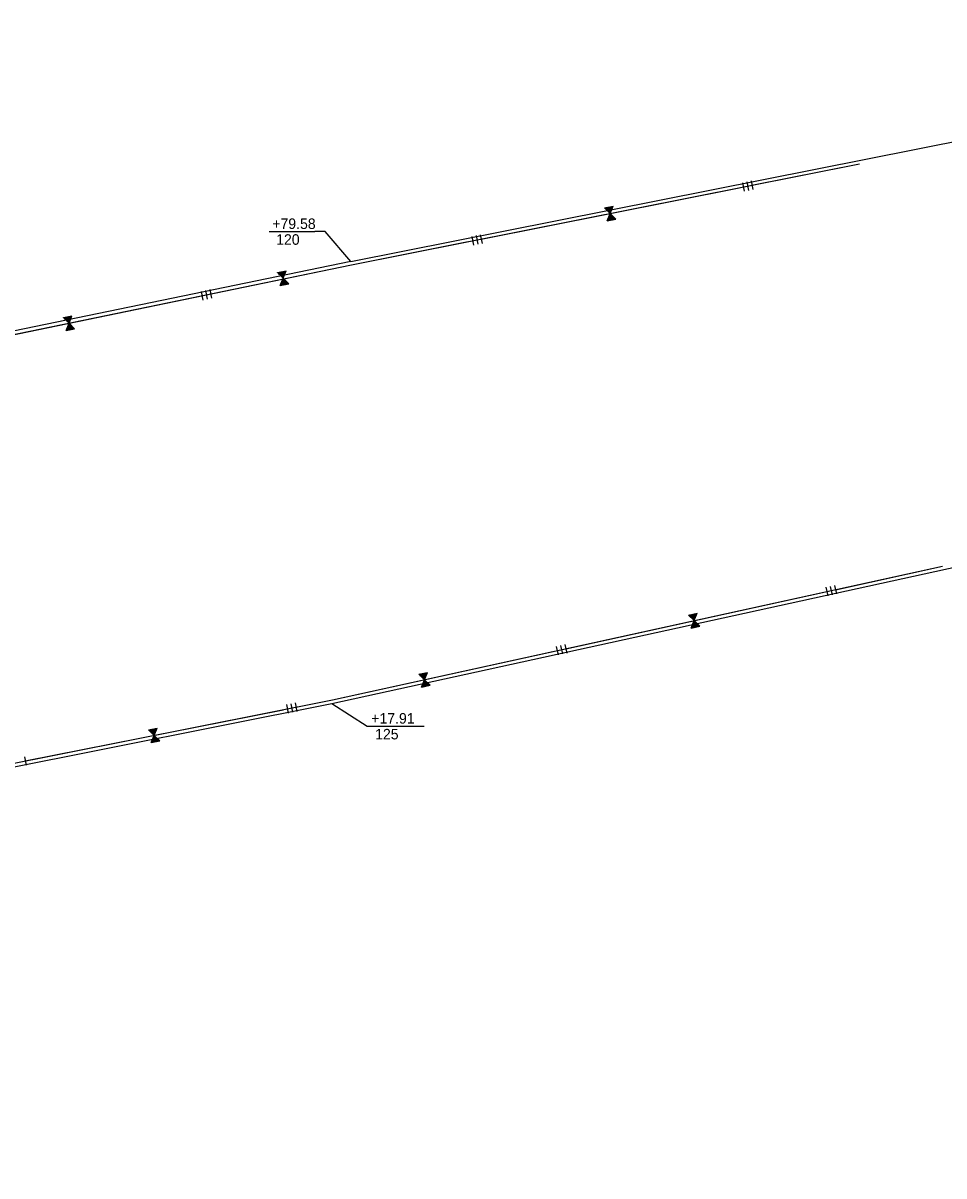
# Model space of a CAD drawing. Extents: x 979729 to 993523, y 1834148 to 1845433.
# Drawn here: x 986339 to 986865, y 1837768 to 1838426 of the extents above; entities that cross this region are included whole.
import ezdxf

# ---------------------------------------------------------------- set-up
doc = ezdxf.new("R2010")
doc.units = 0
for name, color, linetype in [('42', 7, 'Continuous'), ('51', 7, 'Continuous'), ('R_Draft', 7, 'Continuous')]:
    doc.layers.add(name, color=color, linetype=linetype)

msp = doc.modelspace()

# ---------------------------------------------------------------- linework, layer by layer
at = {"layer": '42'}
for p, q in [((986526.66, 1838287.95), (986816.42, 1838345.6)), ((986749.71, 1838334.87), (986750.68, 1838329.97)), ((986752.16, 1838335.36), (986753.13, 1838330.46)), ((986754.61, 1838335.85), (986755.59, 1838330.95)), ((986671, 1838320.49), (986674.18, 1838317.3)), ((986671.07, 1838320.45), (986671.09, 1838320.51)), ((986671.27, 1838320.27), (986671.39, 1838320.57)), ((986671.45, 1838320.06), (986671.68, 1838320.62)), ((986671.65, 1838319.89), (986671.98, 1838320.68)), ((986671.83, 1838319.68), (986672.27, 1838320.74)), ((986672.02, 1838319.47), (986672.57, 1838320.8)), ((986672.22, 1838319.3), (986672.86, 1838320.86)), ((986672.44, 1838319.18), (986673.09, 1838320.76)), ((986672.61, 1838318.94), (986673.45, 1838320.98)), ((986672.81, 1838318.77), (986673.74, 1838321.03)), ((986672.98, 1838318.53), (986674.04, 1838321.09)), ((986673.19, 1838318.38), (986674.33, 1838321.15)), ((986673.36, 1838318.15), (986674.63, 1838321.21)), ((986673.56, 1838317.98), (986674.92, 1838321.27)), ((986673.75, 1838317.76), (986675.22, 1838321.33)), ((986673.96, 1838317.62), (986675.51, 1838321.39)), ((986674.13, 1838317.38), (986675.81, 1838321.44)), ((986674.18, 1838317.3), (986675.9, 1838321.46)), ((986672.46, 1838313.13), (986674.18, 1838317.3)), ((986672.51, 1838313.2), (986672.56, 1838313.15)), ((986672.63, 1838313.43), (986672.85, 1838313.21)), ((986672.72, 1838313.7), (986673.14, 1838313.27)), ((986672.83, 1838313.93), (986673.44, 1838313.33)), ((986672.92, 1838314.2), (986673.73, 1838313.39)), ((986673.01, 1838314.46), (986674.03, 1838313.44)), ((986673.13, 1838314.7), (986674.32, 1838313.5)), ((986673.29, 1838314.89), (986674.5, 1838313.68)), ((986673.36, 1838315.18), (986674.91, 1838313.62)), ((986673.48, 1838315.41), (986675.21, 1838313.68)), ((986673.54, 1838315.7), (986675.5, 1838313.74)), ((986673.68, 1838315.92), (986675.8, 1838313.8)), ((986673.75, 1838316.2), (986676.09, 1838313.85)), ((986673.87, 1838316.44), (986676.39, 1838313.91)), ((986673.96, 1838316.7), (986676.68, 1838313.97)), ((986674.1, 1838316.92), (986676.98, 1838314.03)), ((986674.16, 1838317.2), (986677.27, 1838314.09)), ((986674.18, 1838317.3), (986677.37, 1838314.11)), ((986597.69, 1838304.63), (986598.66, 1838299.72)), ((986600.14, 1838305.11), (986601.11, 1838300.21)), ((986595.23, 1838304.14), (986596.21, 1838299.23)), ((985983.54, 1838175.82), (986526.67, 1838287.95)), ((986487.41, 1838280.68), (986488.94, 1838284.45)), ((986487.58, 1838280.44), (986489.23, 1838284.52)), ((986487.64, 1838280.36), (986489.33, 1838284.54)), ((986484.43, 1838283.52), (986487.64, 1838280.36)), ((986484.5, 1838283.48), (986484.52, 1838283.54)), ((986484.7, 1838283.31), (986484.82, 1838283.6)), ((986484.88, 1838283.1), (986485.11, 1838283.66)), ((986485.09, 1838282.93), (986485.41, 1838283.73)), ((986485.27, 1838282.72), (986485.7, 1838283.79)), ((986485.46, 1838282.51), (986486, 1838283.85)), ((986485.66, 1838282.34), (986486.29, 1838283.91)), ((986485.88, 1838282.23), (986486.52, 1838283.81)), ((986485.95, 1838276.18), (986487.64, 1838280.36)), ((986486.05, 1838281.99), (986486.88, 1838284.03)), ((986486.25, 1838281.82), (986487.17, 1838284.09)), ((986486.43, 1838281.58), (986487.47, 1838284.15)), ((986486.64, 1838281.44), (986487.76, 1838284.21)), ((986486.77, 1838277.94), (986487.98, 1838276.74)), ((986486.81, 1838281.2), (986488.06, 1838284.27)), ((986486.83, 1838278.23), (986488.39, 1838276.68)), ((986486.94, 1838278.47), (986488.69, 1838276.75)), ((986487.01, 1838281.03), (986488.35, 1838284.33)), ((986487.01, 1838278.75), (986488.98, 1838276.81)), ((986487.15, 1838278.97), (986489.28, 1838276.87)), ((986487.2, 1838280.82), (986488.64, 1838284.39)), ((986487.21, 1838279.26), (986489.57, 1838276.93)), ((986487.33, 1838279.49), (986489.87, 1838276.99)), ((986487.42, 1838279.76), (986490.16, 1838277.05)), ((986487.55, 1838279.97), (986490.45, 1838277.11)), ((986487.62, 1838280.26), (986490.75, 1838277.17)), ((986487.64, 1838280.36), (986490.85, 1838277.19)), ((986440.88, 1838272.79), (986441.89, 1838267.89)), ((986443.33, 1838273.29), (986444.34, 1838268.4)), ((986445.78, 1838273.8), (986446.79, 1838268.9)), ((986485.99, 1838276.24), (986486.04, 1838276.2)), ((986486.11, 1838276.48), (986486.34, 1838276.26)), ((986486.2, 1838276.75), (986486.63, 1838276.32)), ((986486.31, 1838276.98), (986486.92, 1838276.38)), ((986486.4, 1838277.25), (986487.22, 1838276.44)), ((986486.49, 1838277.51), (986487.51, 1838276.5)), ((986486.6, 1838277.75), (986487.81, 1838276.56)), ((986363.31, 1838256.83), (986363.85, 1838258.16)), ((986363.51, 1838256.66), (986364.14, 1838258.22)), ((986363.73, 1838256.55), (986364.37, 1838258.13)), ((986363.9, 1838256.3), (986364.73, 1838258.34)), ((986364.1, 1838256.13), (986365.02, 1838258.4)), ((986364.28, 1838255.9), (986365.32, 1838258.47)), ((986364.49, 1838255.75), (986365.61, 1838258.53)), ((986364.66, 1838255.52), (986365.91, 1838258.59)), ((986364.86, 1838255.35), (986366.2, 1838258.65)), ((986365.05, 1838255.14), (986366.49, 1838258.71)), ((986365.26, 1838254.99), (986366.79, 1838258.77)), ((986365.43, 1838254.76), (986367.08, 1838258.83)), ((986365.49, 1838254.67), (986367.18, 1838258.85)), ((986362.28, 1838257.84), (986365.49, 1838254.67)), ((986362.35, 1838257.8), (986362.37, 1838257.86)), ((986362.55, 1838257.63), (986362.67, 1838257.92)), ((986362.73, 1838257.42), (986362.96, 1838257.98)), ((986362.94, 1838257.25), (986363.26, 1838258.04)), ((986363.12, 1838257.04), (986363.55, 1838258.1)), ((986363.8, 1838250.49), (986365.49, 1838254.67)), ((986364.25, 1838251.56), (986365.07, 1838250.76)), ((986364.34, 1838251.83), (986365.36, 1838250.82)), ((986364.45, 1838252.07), (986365.66, 1838250.88)), ((986364.62, 1838252.26), (986365.83, 1838251.06)), ((986364.68, 1838252.55), (986366.24, 1838251)), ((986364.79, 1838252.78), (986366.54, 1838251.06)), ((986364.86, 1838253.07), (986366.83, 1838251.12)), ((986365, 1838253.29), (986367.13, 1838251.18)), ((986365.06, 1838253.57), (986367.42, 1838251.24)), ((986365.18, 1838253.81), (986367.72, 1838251.3)), ((986365.27, 1838254.07), (986368.01, 1838251.36)), ((986365.4, 1838254.29), (986368.3, 1838251.42)), ((986365.47, 1838254.57), (986368.6, 1838251.48)), ((986365.49, 1838254.67), (986368.7, 1838251.51)), ((986363.84, 1838250.56), (986363.89, 1838250.51)), ((986363.96, 1838250.8), (986364.18, 1838250.57)), ((986364.05, 1838251.06), (986364.48, 1838250.63)), ((986364.16, 1838251.3), (986364.77, 1838250.7)), ((986515.73, 1838039.61), (986863.84, 1838115.91)), ((986797.33, 1838103.89), (986798.4, 1838099)), ((986799.77, 1838104.42), (986800.84, 1838099.54)), ((986802.21, 1838104.96), (986803.28, 1838100.07)), ((986718.92, 1838087.98), (986722.16, 1838084.85)), ((986718.98, 1838087.94), (986719.01, 1838088)), ((986719.19, 1838087.77), (986719.3, 1838088.06)), ((986719.37, 1838087.56), (986719.59, 1838088.13)), ((986719.58, 1838087.4), (986719.89, 1838088.19)), ((986719.76, 1838087.19), (986720.18, 1838088.26)), ((986719.95, 1838086.98), (986720.47, 1838088.32)), ((986720.15, 1838086.81), (986720.77, 1838088.39)), ((986720.38, 1838086.7), (986721, 1838088.3)), ((986720.55, 1838086.46), (986721.35, 1838088.52)), ((986720.76, 1838086.29), (986721.65, 1838088.58)), ((986720.93, 1838086.06), (986721.94, 1838088.64)), ((986721.15, 1838085.92), (986722.24, 1838088.71)), ((986721.32, 1838085.69), (986722.53, 1838088.77)), ((986721.52, 1838085.52), (986722.82, 1838088.84)), ((986721.71, 1838085.31), (986723.11, 1838088.9)), ((986721.93, 1838085.17), (986723.41, 1838088.97)), ((986722.1, 1838084.94), (986723.7, 1838089.03)), ((986722.16, 1838084.85), (986723.8, 1838089.05)), ((986720.52, 1838080.65), (986722.16, 1838084.85)), ((986720.56, 1838080.72), (986720.61, 1838080.67)), ((986720.68, 1838080.96), (986720.91, 1838080.74)), ((986720.76, 1838081.22), (986721.2, 1838080.8)), ((986720.88, 1838081.46), (986721.49, 1838080.87)), ((986720.96, 1838081.73), (986721.79, 1838080.93)), ((986721.04, 1838081.99), (986722.08, 1838081)), ((986721.16, 1838082.23), (986722.37, 1838081.06)), ((986721.32, 1838082.43), (986722.55, 1838081.24)), ((986721.37, 1838082.72), (986722.96, 1838081.19)), ((986721.49, 1838082.96), (986723.25, 1838081.25)), ((986721.55, 1838083.24), (986723.55, 1838081.32)), ((986721.68, 1838083.46), (986723.84, 1838081.38)), ((986721.75, 1838083.75), (986724.13, 1838081.45)), ((986721.86, 1838083.98), (986724.43, 1838081.51)), ((986721.95, 1838084.25), (986724.72, 1838081.57)), ((986722.08, 1838084.47), (986725.01, 1838081.64)), ((986722.14, 1838084.75), (986725.31, 1838081.7)), ((986722.16, 1838084.85), (986725.4, 1838081.73)), ((986643.48, 1838070.17), (986644.55, 1838065.28)), ((986645.92, 1838070.7), (986646.99, 1838065.82)), ((986648.36, 1838071.24), (986649.43, 1838066.35)), ((986565.07, 1838054.26), (986568.31, 1838051.13)), ((986565.13, 1838054.22), (986565.16, 1838054.28)), ((986565.34, 1838054.05), (986565.45, 1838054.34)), ((986565.52, 1838053.84), (986565.75, 1838054.41)), ((986565.73, 1838053.67), (986566.04, 1838054.47)), ((986565.91, 1838053.47), (986566.33, 1838054.54)), ((986566.1, 1838053.26), (986566.63, 1838054.6)), ((986566.3, 1838053.09), (986566.92, 1838054.67)), ((986566.53, 1838052.98), (986567.15, 1838054.58)), ((986566.71, 1838052.74), (986567.51, 1838054.79)), ((986566.91, 1838052.57), (986567.8, 1838054.86)), ((986567.08, 1838052.34), (986568.09, 1838054.92)), ((986567.3, 1838052.2), (986568.39, 1838054.99)), ((986567.48, 1838051.96), (986568.68, 1838055.05)), ((986567.68, 1838051.8), (986568.97, 1838055.12)), ((986567.86, 1838051.59), (986569.27, 1838055.18)), ((986568.08, 1838051.45), (986569.56, 1838055.24)), ((986568.26, 1838051.21), (986569.85, 1838055.31)), ((986568.31, 1838051.13), (986569.95, 1838055.33)), ((986566.67, 1838046.93), (986568.31, 1838051.13)), ((986567.03, 1838047.74), (986567.65, 1838047.15)), ((986567.11, 1838048.01), (986567.94, 1838047.21)), ((986567.2, 1838048.27), (986568.23, 1838047.28)), ((986567.31, 1838048.51), (986568.53, 1838047.34)), ((986567.47, 1838048.7), (986568.7, 1838047.52)), ((986567.53, 1838049), (986569.11, 1838047.47)), ((986567.64, 1838049.23), (986569.41, 1838047.53)), ((986567.7, 1838049.52), (986569.7, 1838047.6)), ((986567.84, 1838049.74), (986569.99, 1838047.66)), ((986567.9, 1838050.02), (986570.29, 1838047.73)), ((986568.01, 1838050.26), (986570.58, 1838047.79)), ((986568.1, 1838050.53), (986570.87, 1838047.85)), ((986568.23, 1838050.75), (986571.17, 1838047.92)), ((986568.29, 1838051.03), (986571.46, 1838047.98)), ((986568.31, 1838051.13), (986571.56, 1838048)), ((986566.72, 1838047), (986566.76, 1838046.95)), ((986566.83, 1838047.24), (986567.06, 1838047.02)), ((986566.91, 1838047.5), (986567.35, 1838047.08)), ((986031.55, 1837943.3), (986515.73, 1838039.61)), ((986489.58, 1838036.95), (986490.55, 1838032.05)), ((986492.03, 1838037.44), (986493, 1838032.54)), ((986494.48, 1838037.93), (986495.45, 1838033.02)), ((986410.87, 1838022.57), (986414.05, 1838019.38)), ((986410.94, 1838022.53), (986410.96, 1838022.59)), ((986411.13, 1838022.36), (986411.26, 1838022.65)), ((986411.32, 1838022.15), (986411.55, 1838022.71)), ((986411.52, 1838021.97), (986411.84, 1838022.77)), ((986411.7, 1838021.76), (986412.14, 1838022.82)), ((986411.88, 1838021.55), (986412.43, 1838022.88)), ((986412.08, 1838021.38), (986412.73, 1838022.94)), ((986412.31, 1838021.27), (986412.96, 1838022.85)), ((986412.48, 1838021.02), (986413.32, 1838023.06)), ((986412.68, 1838020.85), (986413.61, 1838023.12)), ((986412.85, 1838020.61), (986413.91, 1838023.18)), ((986413.06, 1838020.47), (986414.2, 1838023.23)), ((986413.23, 1838020.23), (986414.5, 1838023.29)), ((986413.43, 1838020.06), (986414.79, 1838023.35)), ((986413.61, 1838019.85), (986415.09, 1838023.41)), ((986413.82, 1838019.7), (986415.38, 1838023.47)), ((986414, 1838019.47), (986415.67, 1838023.53)), ((986414.05, 1838019.38), (986415.77, 1838023.55)), ((986412.33, 1838015.22), (986414.05, 1838019.38)), ((986412.38, 1838015.28), (986412.42, 1838015.23)), ((986412.5, 1838015.52), (986412.72, 1838015.29)), ((986412.58, 1838015.78), (986413.01, 1838015.35)), ((986412.7, 1838016.02), (986413.31, 1838015.41)), ((986412.79, 1838016.28), (986413.6, 1838015.47)), ((986412.88, 1838016.54), (986413.9, 1838015.53)), ((986413, 1838016.78), (986414.19, 1838015.59)), ((986413.16, 1838016.97), (986414.37, 1838015.76)), ((986413.23, 1838017.26), (986414.78, 1838015.7)), ((986413.34, 1838017.5), (986415.08, 1838015.76)), ((986413.41, 1838017.78), (986415.37, 1838015.82)), ((986413.55, 1838018), (986415.67, 1838015.88)), ((986413.62, 1838018.28), (986415.96, 1838015.94)), ((986413.74, 1838018.52), (986416.25, 1838016)), ((986413.83, 1838018.78), (986416.55, 1838016.05)), ((986413.96, 1838019), (986416.84, 1838016.11)), ((986414.03, 1838019.28), (986417.14, 1838016.17)), ((986414.05, 1838019.38), (986417.24, 1838016.19)), ((986340.01, 1838007.2), (986340.98, 1838002.3))]:
    msp.add_line(p, q, dxfattribs=at)
for points in [[(986755.1, 1838333.4), (986816.42, 1838345.6)], [(986600.63, 1838302.66), (986747.74, 1838331.93)], [(986671, 1838320.49), (986675.9, 1838321.46)], [(986672.46, 1838313.13), (986677.37, 1838314.11)], [(986526.66, 1838287.95), (986593.27, 1838301.2)], [(986292.04, 1838239.51), (986526.66, 1838287.95)], [(986484.43, 1838283.52), (986489.33, 1838284.54)], [(986485.95, 1838276.18), (986490.85, 1838277.19)], [(986362.28, 1838257.84), (986367.18, 1838258.85)], [(986363.8, 1838250.49), (986368.7, 1838251.51)], [(986802.75, 1838102.52), (986863.84, 1838115.91)], [(986648.9, 1838068.8), (986795.42, 1838100.91)], [(986718.92, 1838087.98), (986723.8, 1838089.05)], [(986720.52, 1838080.65), (986725.4, 1838081.73)], [(986494.97, 1838035.48), (986515.73, 1838039.61), (986641.57, 1838067.19)], [(986565.07, 1838054.26), (986569.95, 1838055.33)], [(986566.67, 1838046.93), (986571.56, 1838048)], [(986340.49, 1838004.75), (986487.61, 1838034.01)], [(986410.87, 1838022.57), (986415.77, 1838023.55)], [(986412.33, 1838015.22), (986417.24, 1838016.19)]]:
    msp.add_lwpolyline(points, dxfattribs=at)
at = {"layer": '51'}
for p, q in [((986526.26, 1838289.91), (987210.15, 1838425.98)), ((986515.41, 1838037.5), (987317.37, 1838213.27)), ((985159.91, 1837767.88), (986515.41, 1838037.5))]:
    msp.add_line(p, q, dxfattribs=at)
msp.add_lwpolyline([(986526.26, 1838289.91), (985811.75, 1838142.4), (985091.14, 1838121.27)], dxfattribs=at)
at = {"layer": 'R_Draft'}
for p, q in [((986479.67, 1838306.93), (986505.71, 1838306.93)), ((986541.53, 1838024.57), (986568.11, 1838024.57))]:
    msp.add_line(p, q, dxfattribs=at)
for points in [[(986526.26, 1838289.91), (986511.71, 1838306.93), (986505.71, 1838306.93)], [(986515.41, 1838037.5), (986535.53, 1838024.57), (986541.53, 1838024.57)]]:
    msp.add_lwpolyline(points, dxfattribs=at)

# ---------------------------------------------------------------- texts
for s, p in [('+79.58', (986481.44, 1838308.43)), (' 120', (986481.44, 1838299.43)), ('+17.91', (986537.9, 1838026.07)), (' 125', (986537.9, 1838017.07))]:
    msp.add_text(s, height=6, rotation=360, dxfattribs=at).set_placement(p)

doc.saveas('drawing.dxf')
